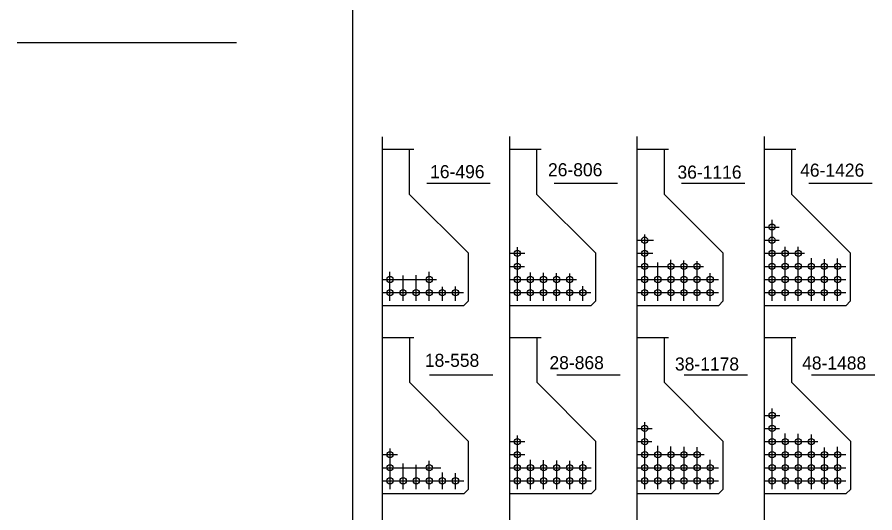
# Model space of a CAD drawing. Extents: x 1005.4 to 1102, y 2007.8 to 2074.2.
# Drawn here: x 1005.42 to 1027.31, y 2029.05 to 2041.69 of the extents above; entities that cross this region are included whole.
import ezdxf

# ---------------------------------------------------------------- set-up
doc = ezdxf.new("R2010")
doc.units = 0
for name, color, linetype in [('Level 1', 7, 'Continuous'), ('Level 37', 7, 'Continuous'), ('Level 8', 7, 'Continuous')]:
    doc.layers.add(name, color=color, linetype=linetype)

msp = doc.modelspace()

# ---------------------------------------------------------------- linework, layer by layer
at = {"layer": 'Level 1'}
msp.add_line((1013.989, 2013.041), (1013.989, 2069.04), dxfattribs=at)
at = {"layer": 'Level 37'}
msp.add_line((1011.017, 2041.04), (1005.42, 2041.04), dxfattribs=at)
at = {"layer": 'Level 8'}
for p, q in [((1014.732, 2038.643), (1014.739, 2014.968)), ((1017.982, 2038.644), (1017.989, 2014.969)), ((1021.232, 2038.645), (1021.239, 2014.97)), ((1024.482, 2038.646), (1024.489, 2014.971)), ((1014.731, 2038.326), (1015.539, 2038.326)), ((1014.767, 2038.326), (1015.539, 2038.326)), ((1015.434, 2037.172), (1015.434, 2038.326)), ((1017.981, 2038.326), (1018.789, 2038.326)), ((1018.017, 2038.326), (1018.789, 2038.326)), ((1018.684, 2037.172), (1018.684, 2038.326)), ((1021.231, 2038.326), (1022.039, 2038.326)), ((1021.267, 2038.326), (1022.039, 2038.326)), ((1021.934, 2037.172), (1021.934, 2038.326)), ((1024.481, 2038.326), (1025.289, 2038.326)), ((1024.517, 2038.326), (1025.289, 2038.326)), ((1025.184, 2037.172), (1025.184, 2038.326)), ((1015.871, 2037.454), (1017.487, 2037.454)), ((1019.121, 2037.454), (1020.737, 2037.454)), ((1019.121, 2037.454), (1020.737, 2037.454)), ((1022.371, 2037.454), (1023.987, 2037.454)), ((1022.371, 2037.454), (1023.987, 2037.454)), ((1022.371, 2037.454), (1023.987, 2037.454)), ((1025.621, 2037.454), (1027.237, 2037.454)), ((1025.621, 2037.454), (1027.237, 2037.454)), ((1025.621, 2037.454), (1027.237, 2037.454)), ((1025.621, 2037.454), (1027.237, 2037.454)), ((1016.938, 2035.669), (1015.434, 2037.172)), ((1020.188, 2035.669), (1018.684, 2037.172)), ((1023.438, 2035.669), (1021.934, 2037.172)), ((1026.688, 2035.669), (1025.184, 2037.172)), ((1024.683, 2034.458), (1024.683, 2036.522)), ((1024.482, 2036.337), (1024.86, 2036.337)), ((1021.433, 2034.458), (1021.433, 2036.149)), ((1021.232, 2036.003), (1021.657, 2036.003)), ((1024.482, 2036.003), (1024.86, 2036.003)), ((1025.018, 2034.458), (1025.018, 2035.836)), ((1025.351, 2034.458), (1025.351, 2035.836)), ((1016.938, 2034.458), (1016.938, 2035.669)), ((1017.982, 2035.669), (1018.377, 2035.669)), ((1018.183, 2034.458), (1018.183, 2035.823)), ((1020.188, 2034.458), (1020.188, 2035.669)), ((1021.232, 2035.669), (1021.641, 2035.669)), ((1023.438, 2034.458), (1023.438, 2035.669)), ((1024.482, 2035.669), (1025.509, 2035.669)), ((1026.688, 2034.458), (1026.688, 2035.669)), ((1021.768, 2034.458), (1021.768, 2035.438)), ((1022.101, 2034.458), (1022.101, 2035.503)), ((1022.435, 2034.458), (1022.435, 2035.486)), ((1022.769, 2034.458), (1022.769, 2035.469)), ((1025.685, 2034.458), (1025.685, 2035.543)), ((1026.019, 2034.458), (1026.019, 2035.519)), ((1026.354, 2034.458), (1026.354, 2035.533)), ((1014.933, 2034.458), (1014.933, 2035.196)), ((1015.935, 2034.458), (1015.935, 2035.196)), ((1017.983, 2035.335), (1018.362, 2035.335)), ((1018.518, 2034.458), (1018.518, 2035.182)), ((1018.851, 2034.458), (1018.851, 2035.172)), ((1021.233, 2035.335), (1022.937, 2035.335)), ((1024.483, 2035.335), (1026.562, 2035.335)), ((1014.733, 2035.001), (1016.118, 2035.001)), ((1015.268, 2034.458), (1015.268, 2035.105)), ((1015.601, 2034.458), (1015.601, 2035.115)), ((1017.983, 2035.001), (1019.691, 2035.001)), ((1019.185, 2034.458), (1019.185, 2035.163)), ((1019.519, 2034.458), (1019.519, 2035.153)), ((1021.233, 2035.001), (1023.312, 2035.001)), ((1023.104, 2034.458), (1023.104, 2035.161)), ((1024.483, 2035.001), (1026.562, 2035.001)), ((1016.269, 2034.458), (1016.269, 2034.817)), ((1016.604, 2034.458), (1016.604, 2034.821)), ((1019.854, 2034.458), (1019.854, 2034.832)), ((1014.733, 2034.667), (1016.812, 2034.667)), ((1017.983, 2034.667), (1020.062, 2034.667)), ((1021.233, 2034.667), (1023.312, 2034.667)), ((1024.483, 2034.667), (1026.562, 2034.667)), ((1016.812, 2034.333), (1014.733, 2034.333)), ((1016.812, 2034.333), (1016.938, 2034.458)), ((1020.062, 2034.333), (1017.983, 2034.333)), ((1020.062, 2034.333), (1020.188, 2034.458)), ((1023.312, 2034.333), (1021.233, 2034.333)), ((1023.312, 2034.333), (1023.438, 2034.458)), ((1026.562, 2034.333), (1024.483, 2034.333)), ((1026.562, 2034.333), (1026.688, 2034.458)), ((1014.733, 2033.526), (1015.541, 2033.526)), ((1014.768, 2033.526), (1015.541, 2033.526)), ((1015.436, 2032.372), (1015.436, 2033.526)), ((1017.983, 2033.526), (1018.791, 2033.526)), ((1018.018, 2033.526), (1018.791, 2033.526)), ((1018.686, 2032.372), (1018.686, 2033.526)), ((1021.233, 2033.526), (1022.041, 2033.526)), ((1021.268, 2033.526), (1022.041, 2033.526)), ((1021.936, 2032.372), (1021.936, 2033.526)), ((1024.483, 2033.526), (1025.291, 2033.526)), ((1024.518, 2033.526), (1025.291, 2033.526)), ((1025.186, 2032.372), (1025.186, 2033.526)), ((1015.94, 2032.568), (1017.556, 2032.568)), ((1019.19, 2032.568), (1020.806, 2032.568)), ((1019.19, 2032.568), (1020.806, 2032.568)), ((1022.44, 2032.568), (1024.056, 2032.568)), ((1022.44, 2032.568), (1024.056, 2032.568)), ((1022.44, 2032.568), (1024.056, 2032.568)), ((1025.69, 2032.568), (1027.306, 2032.568)), ((1025.69, 2032.568), (1027.306, 2032.568)), ((1025.69, 2032.568), (1027.306, 2032.568)), ((1025.69, 2032.568), (1027.306, 2032.568)), ((1016.939, 2030.869), (1015.436, 2032.372)), ((1020.189, 2030.869), (1018.686, 2032.372)), ((1023.439, 2030.869), (1021.936, 2032.372)), ((1026.689, 2030.869), (1025.186, 2032.372)), ((1024.685, 2029.658), (1024.685, 2031.711)), ((1024.484, 2031.537), (1024.879, 2031.537)), ((1021.435, 2029.658), (1021.435, 2031.366)), ((1018.185, 2029.658), (1018.185, 2031.021)), ((1021.234, 2031.203), (1021.621, 2031.203)), ((1024.484, 2031.203), (1024.869, 2031.203)), ((1025.019, 2029.658), (1025.019, 2031.076)), ((1025.353, 2029.658), (1025.353, 2031.063)), ((1025.687, 2029.658), (1025.687, 2031.05)), ((1016.939, 2029.658), (1016.939, 2030.869)), ((1017.984, 2030.869), (1018.374, 2030.869)), ((1020.189, 2029.658), (1020.189, 2030.869)), ((1021.234, 2030.869), (1021.611, 2030.869)), ((1023.439, 2029.658), (1023.439, 2030.869)), ((1024.484, 2030.869), (1025.849, 2030.869)), ((1026.689, 2029.658), (1026.689, 2030.869)), ((1014.935, 2029.658), (1014.935, 2030.694)), ((1021.769, 2029.658), (1021.769, 2030.758)), ((1022.103, 2029.658), (1022.103, 2030.747)), ((1022.437, 2029.658), (1022.437, 2030.735)), ((1022.771, 2029.658), (1022.771, 2030.723)), ((1026.021, 2029.658), (1026.021, 2030.714)), ((1026.355, 2029.658), (1026.355, 2030.733)), ((1014.734, 2030.535), (1015.129, 2030.535)), ((1015.937, 2029.658), (1015.937, 2030.374)), ((1017.984, 2030.535), (1018.374, 2030.535)), ((1018.519, 2029.658), (1018.519, 2030.4)), ((1018.853, 2029.658), (1018.853, 2030.392)), ((1019.187, 2029.658), (1019.187, 2030.385)), ((1019.521, 2029.658), (1019.521, 2030.377)), ((1019.855, 2029.658), (1019.855, 2030.37)), ((1021.234, 2030.535), (1022.954, 2030.535)), ((1023.105, 2029.658), (1023.105, 2030.405)), ((1024.484, 2030.535), (1026.564, 2030.535)), ((1014.734, 2030.201), (1016.229, 2030.201)), ((1015.269, 2029.658), (1015.269, 2030.306)), ((1015.603, 2029.658), (1015.603, 2030.275)), ((1017.984, 2030.201), (1020.064, 2030.201)), ((1021.234, 2030.201), (1023.314, 2030.201)), ((1024.484, 2030.201), (1026.564, 2030.201)), ((1016.271, 2029.658), (1016.271, 2030.078)), ((1016.605, 2029.658), (1016.605, 2030.066)), ((1014.734, 2029.867), (1016.814, 2029.867)), ((1017.984, 2029.867), (1020.064, 2029.867)), ((1021.234, 2029.867), (1023.314, 2029.867)), ((1024.484, 2029.867), (1026.564, 2029.867)), ((1016.814, 2029.533), (1014.734, 2029.533)), ((1016.814, 2029.533), (1016.939, 2029.658)), ((1020.064, 2029.533), (1017.984, 2029.533)), ((1020.064, 2029.533), (1020.189, 2029.658)), ((1023.314, 2029.533), (1021.234, 2029.533)), ((1023.314, 2029.533), (1023.439, 2029.658)), ((1026.564, 2029.533), (1024.484, 2029.533)), ((1026.564, 2029.533), (1026.689, 2029.658))]:
    msp.add_line(p, q, dxfattribs=at)
for centre in [(1024.683, 2036.337), (1021.433, 2036.003), (1024.683, 2036.003), (1018.183, 2035.669), (1021.433, 2035.669), (1024.683, 2035.669), (1025.017, 2035.669), (1025.351, 2035.669), (1018.183, 2035.335), (1021.433, 2035.335), (1022.101, 2035.335), (1022.435, 2035.335), (1022.769, 2035.335), (1024.683, 2035.335), (1025.017, 2035.335), (1025.351, 2035.335), (1025.685, 2035.335), (1026.019, 2035.335), (1026.354, 2035.335), (1014.933, 2035.001), (1015.935, 2035.001), (1018.183, 2035.001), (1018.517, 2035.001), (1018.851, 2035.001), (1019.185, 2035.001), (1019.519, 2035.001), (1021.433, 2035.001), (1021.767, 2035.001), (1022.101, 2035.001), (1022.435, 2035.001), (1022.769, 2035.001), (1023.104, 2035.001), (1024.683, 2035.001), (1025.017, 2035.001), (1025.351, 2035.001), (1025.685, 2035.001), (1026.019, 2035.001), (1026.354, 2035.001), (1014.933, 2034.667), (1015.267, 2034.667), (1015.601, 2034.667), (1015.935, 2034.667), (1016.269, 2034.667), (1016.604, 2034.667), (1018.183, 2034.667), (1018.517, 2034.667), (1018.851, 2034.667), (1019.185, 2034.667), (1019.519, 2034.667), (1019.854, 2034.667), (1021.433, 2034.667), (1021.767, 2034.667), (1022.101, 2034.667), (1022.435, 2034.667), (1022.769, 2034.667), (1023.104, 2034.667), (1024.683, 2034.667), (1025.017, 2034.667), (1025.351, 2034.667), (1025.685, 2034.667), (1026.019, 2034.667), (1026.354, 2034.667), (1024.685, 2031.537), (1021.435, 2031.203), (1024.685, 2031.203), (1018.185, 2030.869), (1021.435, 2030.869), (1024.685, 2030.869), (1025.019, 2030.869), (1025.353, 2030.869), (1025.687, 2030.869), (1014.935, 2030.535), (1018.185, 2030.535), (1021.435, 2030.535), (1021.769, 2030.535), (1022.103, 2030.535), (1022.437, 2030.535), (1022.771, 2030.535), (1024.685, 2030.535), (1025.019, 2030.535), (1025.353, 2030.535), (1025.687, 2030.535), (1026.021, 2030.535), (1026.355, 2030.535), (1014.935, 2030.201), (1015.937, 2030.201), (1018.185, 2030.201), (1018.519, 2030.201), (1018.853, 2030.201), (1019.187, 2030.201), (1019.521, 2030.201), (1019.855, 2030.201), (1021.435, 2030.201), (1021.769, 2030.201), (1022.103, 2030.201), (1022.437, 2030.201), (1022.771, 2030.201), (1023.105, 2030.201), (1024.685, 2030.201), (1025.019, 2030.201), (1025.353, 2030.201), (1025.687, 2030.201), (1026.021, 2030.201), (1026.355, 2030.201), (1014.935, 2029.867), (1015.269, 2029.867), (1015.603, 2029.867), (1015.937, 2029.867), (1016.271, 2029.867), (1016.605, 2029.867), (1018.185, 2029.867), (1018.519, 2029.867), (1018.853, 2029.867), (1019.187, 2029.867), (1019.521, 2029.867), (1019.855, 2029.867), (1021.435, 2029.867), (1021.769, 2029.867), (1022.103, 2029.867), (1022.437, 2029.867), (1022.771, 2029.867), (1023.105, 2029.867), (1024.685, 2029.867), (1025.019, 2029.867), (1025.353, 2029.867), (1025.687, 2029.867), (1026.021, 2029.867), (1026.355, 2029.867)]:
    msp.add_circle(centre, 0.0797, dxfattribs=at)

# ---------------------------------------------------------------- texts
for s, p in [('16-496 ', (1015.958, 2037.584)), ('26-806 ', (1018.965, 2037.633)), ('36-1116', (1022.269, 2037.573)), ('46-1426', (1025.4, 2037.623)), ('18-558 ', (1015.824, 2032.774)), ('28-868 ', (1019.003, 2032.713)), ('38-1178', (1022.205, 2032.68)), ('48-1488', (1025.45, 2032.705))]:
    msp.add_text(s, height=0.3333, dxfattribs=at).set_placement(p)

doc.saveas('drawing.dxf')
